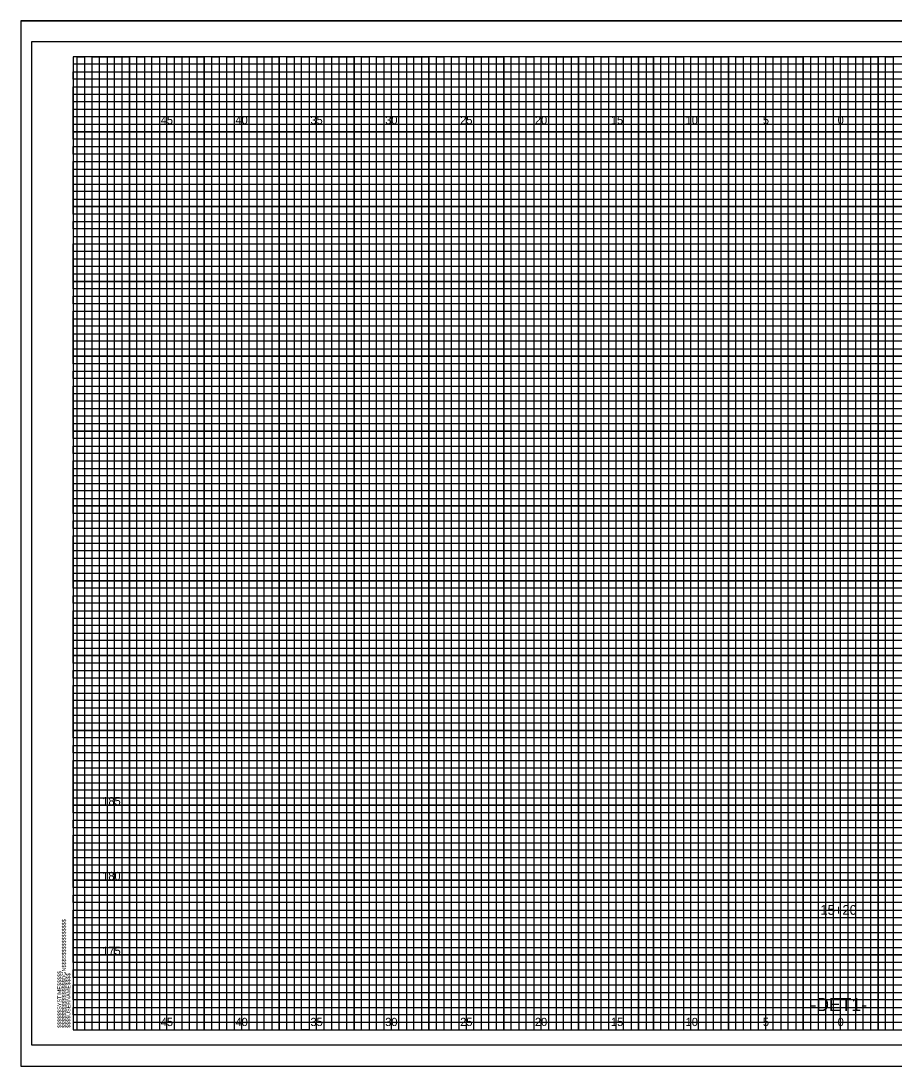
# Model space of a CAD drawing. Extents: x -4 to 103, y -2 to 280.
# Drawn here: x -3.5 to 54.8, y 210.1 to 279.9 of the extents above; entities that cross this region are included whole.
import ezdxf

# ---------------------------------------------------------------- set-up
doc = ezdxf.new("R2010")
doc.units = 0
for name, color, linetype in [('Exist XS Center Line Elevation Label', 7, 'Continuous'), ('Old_Level_63', 7, 'Continuous'), ('Prop XS Dump Level', 7, 'Continuous'), ('Prop XS EOT Tick Mark', 7, 'Continuous'), ('Prop XS Finish Grade Earthwork', 7, 'Continuous'), ('Prop XS Pvmt Edge Slope', 7, 'Continuous'), ('Prop XS SE Text', 7, 'Continuous'), ('Prop XS Subgrade Earthwork', 7, 'Continuous'), ('Sheet Cutting Line CELL', 7, 'Continuous'), ('Sheet Plot Border Inside CELL', 7, 'Continuous'), ('Sheet Plot Border Outside CELL', 7, 'Continuous')]:
    doc.layers.add(name, color=color, linetype=linetype)

msp = doc.modelspace()

# ---------------------------------------------------------------- linework, layer by layer
at = {"layer": 'Exist XS Center Line Elevation Label'}
for points in [[(1.25, 212.475), (1.25, 277.475), (3.75, 277.475), (3.75, 212.475), (6.25, 212.475), (6.25, 277.475), (8.75, 277.475), (8.75, 212.475), (11.25, 212.475), (11.25, 277.475), (13.75, 277.475), (13.75, 212.475), (16.25, 212.475), (16.25, 277.475), (18.75, 277.475), (18.75, 212.475), (21.25, 212.475), (21.25, 277.475), (23.75, 277.475), (23.75, 212.475), (26.25, 212.475), (26.25, 277.475), (28.75, 277.475), (28.75, 212.475), (31.25, 212.475), (31.25, 277.475), (33.75, 277.475), (33.75, 212.475), (36.25, 212.475), (36.25, 277.475), (38.75, 277.475), (38.75, 212.475), (41.25, 212.475), (41.25, 277.475), (43.75, 277.475), (43.75, 212.475), (46.25, 212.475), (46.25, 277.475), (48.75, 277.475), (48.75, 212.475), (51.25, 212.475), (51.25, 277.475), (53.75, 277.475), (53.75, 212.475)], [(102.5, 272.475), (0, 272.475), (0, 274.975), (74.25, 274.975)], [(102.5, 267.475), (0, 267.475), (0, 269.975), (102.5, 269.975)], [(102.5, 262.475), (0, 262.475), (0, 264.975), (102.5, 264.975)], [(102.5, 257.475), (0, 257.475), (0, 259.975), (102.5, 259.975)], [(102.5, 252.475), (0, 252.475), (0, 254.975), (102.5, 254.975)], [(102.5, 247.475), (0, 247.475), (0, 249.975), (102.5, 249.975)], [(102.5, 242.475), (0, 242.475), (0, 244.975), (102.5, 244.975)], [(102.5, 237.475), (0, 237.475), (0, 239.975), (102.5, 239.975)], [(102.5, 232.475), (0, 232.475), (0, 234.975), (102.5, 234.975)], [(102.5, 227.475), (0, 227.475), (0, 229.975), (102.5, 229.975)], [(102.5, 222.475), (0, 222.475), (0, 224.975), (102.5, 224.975)], [(102.5, 217.475), (0, 217.475), (0, 219.975), (102.5, 219.975)], [(0, 214.975), (102.5, 214.975)]]:
    msp.add_lwpolyline(points, dxfattribs=at)
at = {"layer": 'Old_Level_63'}
msp.add_lwpolyline([(102.5, 277.475), (0, 277.475), (0, 212.475), (102.5, 212.475)], close=True, dxfattribs=at)
at = {"layer": 'Prop XS Dump Level'}
for p, q in [((1.25, 212.475), (1.25, 277.475)), ((3.75, 212.475), (3.75, 277.475)), ((6.25, 212.475), (6.25, 277.475)), ((8.75, 212.475), (8.75, 277.475)), ((11.25, 212.475), (11.25, 277.475)), ((13.75, 212.475), (13.75, 277.475)), ((16.25, 212.475), (16.25, 277.475)), ((18.75, 212.475), (18.75, 277.475)), ((21.25, 212.475), (21.25, 277.475)), ((23.75, 212.475), (23.75, 277.475)), ((26.25, 212.475), (26.25, 277.475)), ((28.75, 212.475), (28.75, 277.475)), ((31.25, 212.475), (31.25, 277.475)), ((33.75, 212.475), (33.75, 277.475)), ((36.25, 212.475), (36.25, 277.475)), ((38.75, 212.475), (38.75, 277.475)), ((41.25, 212.475), (41.25, 277.475)), ((43.75, 212.475), (43.75, 277.475)), ((46.25, 212.475), (46.25, 277.475)), ((48.75, 212.475), (48.75, 277.475)), ((51.25, 212.475), (51.25, 277.475)), ((53.75, 212.475), (53.75, 277.475)), ((0, 274.975), (74.25, 274.975)), ((0, 272.475), (102.5, 272.475)), ((0, 269.975), (102.5, 269.975)), ((0, 267.475), (102.5, 267.475)), ((0, 264.975), (102.5, 264.975)), ((0, 262.475), (102.5, 262.475)), ((0, 259.975), (102.5, 259.975)), ((0, 257.475), (102.5, 257.475)), ((0, 254.975), (102.5, 254.975)), ((0, 252.475), (102.5, 252.475)), ((0, 249.975), (102.5, 249.975)), ((0, 247.475), (102.5, 247.475)), ((0, 244.975), (102.5, 244.975)), ((0, 242.475), (102.5, 242.475)), ((0, 239.975), (102.5, 239.975)), ((0, 237.475), (102.5, 237.475)), ((0, 234.975), (102.5, 234.975)), ((0, 232.475), (102.5, 232.475)), ((0, 229.975), (102.5, 229.975)), ((0, 227.475), (102.5, 227.475)), ((0, 224.975), (102.5, 224.975)), ((0, 222.475), (102.5, 222.475)), ((0, 219.975), (102.5, 219.975)), ((0, 217.475), (102.5, 217.475)), ((0, 214.975), (102.5, 214.975))]:
    msp.add_line(p, q, dxfattribs=at)
at = {"layer": 'Prop XS SE Text'}
for points in [[(0.25, 212.475), (0.25, 277.475), (0.75, 277.475), (0.75, 212.475), (1.75, 212.475), (1.75, 277.475), (2.25, 277.475), (2.25, 212.475), (2.75, 212.475), (2.75, 277.475), (3.25, 277.475), (3.25, 212.475), (4.25, 212.475), (4.25, 277.475), (4.75, 277.475), (4.75, 212.475), (5.25, 212.475), (5.25, 277.475), (5.75, 277.475), (5.75, 212.475), (6.75, 212.475), (6.75, 277.475), (7.25, 277.475), (7.25, 212.475), (7.75, 212.475), (7.75, 277.475), (8.25, 277.475), (8.25, 212.475), (9.25, 212.475), (9.25, 277.475), (9.75, 277.475), (9.75, 212.475), (10.25, 212.475), (10.25, 277.475), (10.75, 277.475), (10.75, 212.475), (11.75, 212.475), (11.75, 277.475), (12.25, 277.475), (12.25, 212.475), (12.75, 212.475), (12.75, 277.475), (13.25, 277.475), (13.25, 212.475), (14.25, 212.475), (14.25, 277.475), (14.75, 277.475), (14.75, 212.475), (15.75, 212.475), (15.25, 212.475), (15.25, 277.475), (15.75, 277.475), (15.75, 212.475), (16.75, 212.475), (16.75, 277.475), (17.25, 277.475), (17.25, 212.475), (17.75, 212.475), (17.75, 277.475), (18.25, 277.475), (18.25, 212.475), (19.25, 212.475), (19.25, 277.475), (19.75, 277.475), (19.75, 212.475), (20.25, 212.475), (20.25, 277.475), (20.75, 277.475), (20.75, 212.475), (21.75, 212.475), (21.75, 277.475), (22.25, 277.475), (22.25, 212.475), (22.75, 212.475), (22.75, 277.475), (23.25, 277.475), (23.25, 212.475), (24.25, 212.475), (24.25, 277.475), (24.75, 277.475), (24.75, 212.475), (25.25, 212.475), (25.25, 277.475), (25.75, 277.475), (25.75, 212.475), (26.75, 212.475), (26.75, 277.475), (27.25, 277.475), (27.25, 212.475), (27.75, 212.475), (27.75, 277.475), (28.25, 277.475), (28.25, 212.475), (29.25, 212.475), (29.25, 277.475), (29.75, 277.475), (29.75, 212.475), (30.25, 212.475), (30.25, 277.475), (30.75, 277.475), (30.75, 212.475)], [(30.75, 212.475), (31.75, 212.475), (31.75, 277.475), (32.25, 277.475), (32.25, 212.475), (32.75, 212.475), (32.75, 277.475), (33.25, 277.475), (33.25, 212.475), (34.25, 212.475), (34.25, 277.475), (34.75, 277.475), (34.75, 212.475), (35.25, 212.475), (35.25, 277.475), (35.75, 277.475), (35.75, 212.475), (36.75, 212.475), (36.75, 277.475), (37.25, 277.475), (37.25, 212.475), (37.75, 212.475), (37.75, 277.475), (37.75, 212.475)], [(38.25, 277.475), (38.25, 212.475), (39.25, 212.475), (39.25, 277.475), (39.75, 277.475), (39.75, 212.475), (40.25, 212.475), (40.25, 277.475), (40.75, 277.475), (40.75, 212.475), (41.75, 212.475), (41.75, 277.475), (42.25, 277.475), (42.25, 212.475), (42.75, 212.475), (42.75, 277.475), (43.25, 277.475), (43.25, 212.475), (43.75, 212.475), (44.25, 212.475), (44.25, 277.475), (44.75, 277.475), (44.75, 212.475), (45.25, 212.475), (45.25, 277.475), (45.75, 277.475), (45.75, 212.475), (46.75, 212.475), (46.75, 277.475), (47.25, 277.475), (47.25, 212.475), (47.75, 212.475), (47.75, 277.475), (48.25, 277.475), (48.25, 212.475), (49.25, 212.475), (49.25, 277.475), (49.75, 277.475), (49.75, 212.475), (50.25, 212.475), (50.25, 277.475), (50.75, 277.475), (50.75, 212.475), (51.75, 212.475), (51.75, 277.475), (52.25, 277.475), (52.25, 212.475), (52.75, 212.475), (52.75, 277.475), (53.25, 277.475), (53.25, 212.475), (54.25, 212.475), (54.25, 277.475), (54.75, 277.475), (54.75, 212.475), (55.25, 212.475)], [(0, 274.475), (0, 275.475), (74.25, 275.475), (74.25, 275.975), (0, 275.975), (0, 276.475), (74.25, 276.475), (74.25, 276.975), (0, 276.975)], [(102.5, 274.475), (0, 274.475)], [(102.5, 273.475), (0, 273.475), (0, 273.975), (102.5, 273.975)], [(102.5, 271.975), (0, 271.975), (0, 272.975), (102.5, 272.975)], [(102.5, 270.975), (0, 270.975), (0, 271.475), (102.5, 271.475)], [(102.5, 269.475), (0, 269.475), (0, 270.475), (102.5, 270.475)], [(102.5, 268.475), (0, 268.475), (0, 268.975), (102.5, 268.975)], [(102.5, 266.975), (0, 266.975), (0, 267.975), (102.5, 267.975)], [(102.5, 265.975), (0, 265.975), (0, 266.475), (102.5, 266.475)], [(0, 265.475), (102.5, 265.475)], [(102.5, 264.475), (0, 264.475)], [(102.5, 263.475), (0, 263.475), (0, 263.975), (102.5, 263.975)], [(102.5, 261.975), (0, 261.975), (0, 262.975), (102.5, 262.975)], [(102.5, 260.975), (0, 260.975), (0, 261.475), (102.5, 261.475)], [(102.5, 259.475), (0, 259.475), (0, 260.475), (102.5, 260.475)], [(102.5, 258.475), (0, 258.475), (0, 258.975), (102.5, 258.975)], [(102.5, 256.975), (0, 256.975), (0, 257.975), (102.5, 257.975)], [(102.5, 255.975), (0, 255.975), (0, 256.475), (102.5, 256.475)], [(102.5, 254.475), (0, 254.475), (0, 255.475), (102.5, 255.475)], [(102.5, 253.475), (0, 253.475), (0, 253.975), (102.5, 253.975)], [(102.5, 251.975), (0, 251.975), (0, 252.975), (102.5, 252.975)], [(102.5, 250.975), (0, 250.975), (0, 251.475), (102.5, 251.475)], [(102.5, 249.475), (0, 249.475), (0, 250.475), (102.5, 250.475)], [(102.5, 248.475), (0, 248.475), (0, 248.975), (102.5, 248.975)], [(102.5, 246.975), (0, 246.975), (0, 247.975), (102.5, 247.975)], [(102.5, 245.975), (0, 245.975), (0, 246.475), (102.5, 246.475)], [(102.5, 244.475), (0, 244.475), (0, 245.475), (102.5, 245.475)], [(102.5, 243.475), (0, 243.475), (0, 243.975)], [(0, 243.975), (102.5, 243.975)], [(102.5, 241.975), (0, 241.975), (0, 242.975), (102.5, 242.975)], [(102.5, 240.975), (0, 240.975), (0, 241.475), (102.5, 241.475)], [(102.5, 239.475), (0, 239.475), (0, 240.475), (102.5, 240.475)], [(102.5, 238.475), (0, 238.475), (0, 238.975), (102.5, 238.975)], [(102.5, 236.975), (0, 236.975), (0, 237.975), (102.5, 237.975)], [(102.5, 235.975), (0, 235.975), (0, 236.475), (102.5, 236.475)], [(102.5, 234.475), (0, 234.475), (0, 235.475), (102.5, 235.475)], [(102.5, 233.475), (0, 233.475), (0, 233.975), (102.5, 233.975)], [(102.5, 231.975), (0, 231.975), (0, 232.975), (102.5, 232.975)], [(102.5, 230.975), (0, 230.975), (0, 231.475), (102.5, 231.475)], [(102.5, 229.475), (0, 229.475), (0, 230.475), (102.5, 230.475)], [(102.5, 228.475), (0, 228.475), (0, 228.975), (102.5, 228.975)], [(102.5, 226.975), (0, 226.975), (0, 227.975), (102.5, 227.975)], [(102.5, 225.975), (0, 225.975), (0, 226.475), (102.5, 226.475)], [(102.5, 224.475), (0, 224.475), (0, 225.475), (102.5, 225.475)], [(102.5, 223.475), (0, 223.475), (0, 223.975), (102.5, 223.975)], [(102.5, 221.975), (0, 221.975), (0, 222.975), (102.5, 222.975)], [(102.5, 220.975), (0, 220.975), (0, 221.475), (102.5, 221.475)], [(102.5, 219.475), (0, 219.475), (0, 220.475), (102.5, 220.475)], [(102.5, 218.475), (0, 218.475), (0, 218.975), (102.5, 218.975)], [(102.5, 216.975), (0, 216.975), (0, 217.975), (102.5, 217.975)], [(102.5, 215.975), (0, 215.975), (0, 216.475), (102.5, 216.475)], [(102.5, 214.475), (0, 214.475), (0, 215.475), (102.5, 215.475)], [(102.5, 213.475), (0, 213.475), (0, 213.975), (102.5, 213.975)], [(0, 212.975), (102.5, 212.975)]]:
    msp.add_lwpolyline(points, dxfattribs=at)
at = {"layer": 'Sheet Cutting Line CELL'}
for p, q in [((-3.5, 279.875), (103.4, 279.875)), ((-3.5, 279.875), (-3.5, 210.05)), ((-3.5, 210.05), (103.4, 210.05))]:
    msp.add_line(p, q, dxfattribs=at)
at = {"layer": 'Sheet Plot Border Inside CELL'}
msp.add_lwpolyline([(103, 278.475), (-2.8, 278.475), (-2.8, 211.475), (103, 211.475)], close=True, dxfattribs=at)
at = {"layer": 'Sheet Plot Border Outside CELL'}
msp.add_lwpolyline([(103.4, 279.875), (-3.5, 279.875), (-3.5, 210.05), (103.4, 210.05)], close=True, dxfattribs=at)

# ---------------------------------------------------------------- texts
at = {"layer": 'Exist XS Center Line Elevation Label'}
msp.add_text('040397', height=0.0025, rotation=90, dxfattribs=at).set_placement((-0.001, 277.461))
at = {"layer": 'Old_Level_63'}
for s, p in [('$$$$$$$$$$$$$$$$DGN$$$$$$$$$$$$$$$$', (-0.5, 212.6)), ('$$$$$$SYSTIME$$$$$', (-0.797, 212.6)), ('$$$$USERNAME$$$$', (-0.2, 212.6))]:
    msp.add_text(s, height=0.2625, rotation=90, dxfattribs=at).set_placement(p)
at = {"layer": 'Prop XS EOT Tick Mark'}
msp.add_text('15+20', height=0.65, dxfattribs=at).set_placement((49.893, 220.157))
at = {"layer": 'Prop XS Finish Grade Earthwork'}
msp.add_text('-DET1-', height=0.875, dxfattribs=at).set_placement((49.238, 213.725))
at = {"layer": 'Prop XS Pvmt Edge Slope'}
for s, p in [('45', (5.84, 272.975)), ('40', (10.831, 272.975)), ('35', (15.84, 272.975)), ('30', (20.831, 272.975)), ('25', (25.84, 272.975)), ('20', (30.831, 272.975)), ('15', (35.906, 272.975)), ('10', (40.897, 272.975)), ('5', (46.057, 272.975)), ('0', (51.049, 272.975)), ('0', (51.049, 272.975)), ('45', (5.84, 212.725)), ('40', (10.831, 212.725)), ('35', (15.84, 212.725)), ('30', (20.831, 212.725)), ('25', (25.84, 212.725)), ('20', (30.831, 212.725)), ('15', (35.906, 212.725)), ('10', (40.897, 212.725)), ('5', (46.057, 212.725)), ('0', (51.049, 212.725)), ('0', (51.049, 212.725))]:
    msp.add_text(s, height=0.55, dxfattribs=at).set_placement(p)
at = {"layer": 'Prop XS Subgrade Earthwork'}
for s, p in [('185', (1.938, 227.475)), ('180', (1.93, 222.475)), ('175', (1.938, 217.475))]:
    msp.add_text(s, height=0.55, dxfattribs=at).set_placement(p)

doc.saveas('drawing.dxf')
